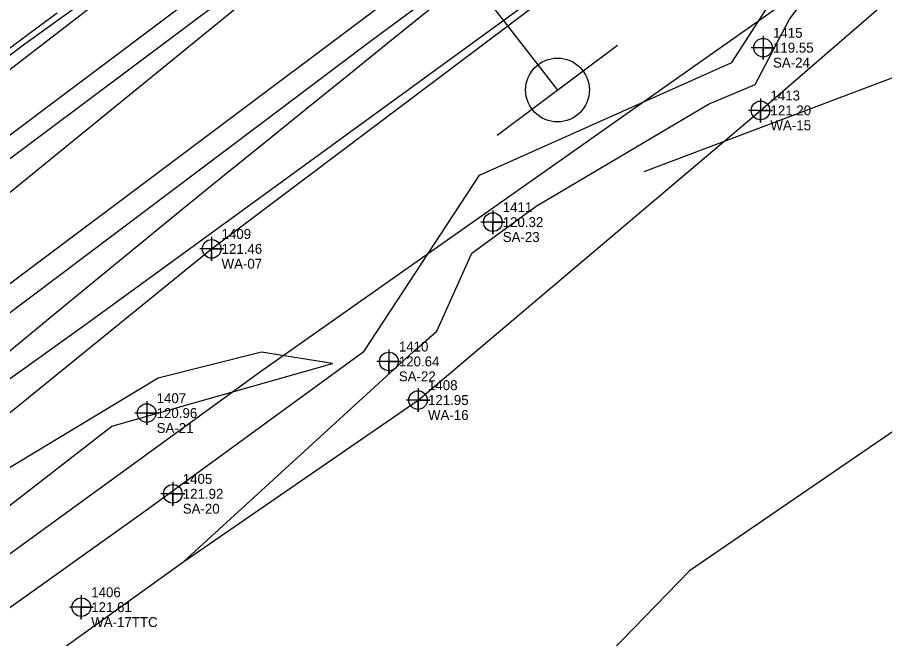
# Model space of a CAD drawing. Extents: x 2186615 to 2188822, y 629899 to 631820.
# Drawn here: x 2187187.8 to 2187253.2, y 630351.9 to 630398.8 of the extents above; entities that cross this region are included whole.
import ezdxf

# ---------------------------------------------------------------- set-up
doc = ezdxf.new("R2010")
doc.units = 0
for name, color, linetype in [('Exist Environmental Wetland Boundary', 7, 'Continuous'), ('Exist Environmental Wetland Boundary Cogo Comment', 7, 'Continuous'), ('Exist Environmental Wetland Boundary Cogo Elevation', 7, 'Continuous'), ('Exist Environmental Wetland Boundary Cogo Number', 7, 'Continuous'), ('Exist Environmental Wetland Boundary Cogo Point CELL', 7, 'Continuous'), ('Exist Environmental Wetland Boundary Leader', 7, 'Continuous'), ('Exist Guardrail', 7, 'Continuous'), ('Exist Hydro Jurisdictional Stream or Body of Water', 7, 'Continuous'), ('Exist Hydro Stream or Body of Water', 7, 'Continuous'), ('Exist Right of Way Line', 7, 'Continuous'), ('Exist Roads EOP', 7, 'Continuous'), ('Exist Roads EOT', 7, 'Continuous'), ('Exist Utilities Sanitary Sewer UG Line', 7, 'Continuous'), ('Exist Utilities Telephone Pole CELL', 7, 'Continuous'), ('Exist Utilities Telephone UG Cable SUE LOS C', 7, 'Continuous'), ('Exist Utilities Telephone UG FO SUE LOS B', 7, 'Continuous'), ('Exist Vegetation Woods Line', 7, 'Continuous'), ('Scratch_Level_1', 7, 'Continuous')]:
    doc.layers.add(name, color=color, linetype=linetype)

msp = doc.modelspace()

# ---------------------------------------------------------------- linework, layer by layer
at = {"layer": 'Exist Environmental Wetland Boundary'}
for points in [[(2187200.333, 630357.676), (2187218.012, 630369.88), (2187243.865, 630391.755), (2187268.738, 630413.3), (2187284.769, 630424.116), (2187304.062, 630440.889), (2187311.728, 630449.237), (2187310.985, 630450.407)], [(2187091.311, 630271.672), (2187085.676, 630287.812), (2187098.271, 630306.167), (2187117.246, 630318.391), (2187145.167, 630331.818), (2187167.383, 630352.861), (2187202.427, 630381.298), (2187228.671, 630401.09), (2187258.21, 630420.516), (2187282.166, 630435.853)]]:
    msp.add_lwpolyline(points, dxfattribs=at)
at = {"layer": 'Exist Environmental Wetland Boundary Cogo Point CELL'}
for points in [[(2187244.056, 630397.391), (2187244.056, 630395.591), (2187244.056, 630396.491), (2187244.956, 630396.491), (2187243.156, 630396.491)], [(2187243.865, 630392.655), (2187243.865, 630390.855), (2187243.865, 630391.755), (2187244.765, 630391.755), (2187242.965, 630391.755)], [(2187223.654, 630384.221), (2187223.654, 630382.421), (2187223.654, 630383.321), (2187224.554, 630383.321), (2187222.754, 630383.321)], [(2187202.427, 630382.198), (2187202.427, 630380.398), (2187202.427, 630381.298), (2187203.327, 630381.298), (2187201.527, 630381.298)], [(2187215.811, 630373.695), (2187215.811, 630371.895), (2187215.811, 630372.795), (2187216.711, 630372.795), (2187214.911, 630372.795)], [(2187218.012, 630370.78), (2187218.012, 630368.98), (2187218.012, 630369.88), (2187218.912, 630369.88), (2187217.112, 630369.88)], [(2187197.525, 630369.798), (2187197.525, 630367.998), (2187197.525, 630368.898), (2187198.425, 630368.898), (2187196.625, 630368.898)], [(2187199.498, 630363.7), (2187199.498, 630361.9), (2187199.498, 630362.8), (2187200.398, 630362.8), (2187198.598, 630362.8)], [(2187192.588, 630355.137), (2187192.588, 630353.337), (2187192.588, 630354.237), (2187193.488, 630354.237), (2187191.688, 630354.237)]]:
    msp.add_lwpolyline(points, dxfattribs=at)
for centre in [(2187244.056, 630396.491), (2187243.865, 630391.755), (2187223.654, 630383.321), (2187202.427, 630381.298), (2187215.811, 630372.795), (2187218.012, 630369.88), (2187197.525, 630368.898), (2187199.498, 630362.8), (2187192.588, 630354.237)]:
    msp.add_circle(centre, 0.703, dxfattribs=at)
at = {"layer": 'Exist Environmental Wetland Boundary Leader'}
msp.add_lwpolyline([(2187235.079, 630387.141), (2187254.322, 630394.422), (2187258.337, 630397.432)], dxfattribs=at)
at = {"layer": 'Exist Guardrail'}
msp.add_lwpolyline([(2187434.115, 630575.844), (2187413.642, 630560.327), (2187392.389, 630544.34), (2187371.189, 630528.329), (2187353.022, 630514.54), (2187332.378, 630498.862), (2187308.035, 630480.517), (2187282.875, 630461.57), (2187260.432, 630444.878), (2187240.787, 630430.164), (2187221.99, 630416.084), (2187199.867, 630399.404), (2187178.435, 630383.307), (2187159.654, 630369.054), (2187143.316, 630356.53), (2187128.809, 630345.412), (2187116.826, 630336.517)], dxfattribs=at)
at = {"layer": 'Exist Hydro Jurisdictional Stream or Body of Water'}
for points in [[(2187197.322, 630361.43), (2187213.945, 630373.562), (2187222.659, 630386.877), (2187241.705, 630395.38), (2187246.836, 630403.358), (2187255.086, 630412.327), (2187267.186, 630417.823), (2187275.409, 630422.294), (2187281.209, 630428.913), (2187281.92, 630435.898), (2187289.055, 630441.644), (2187305.984, 630451.32), (2187327.255, 630464.456), (2187344.34, 630479.914), (2187359.178, 630488.147), (2187368.792, 630495.674), (2187384.724, 630510.856), (2187399.768, 630521.857), (2187428.248, 630541.272), (2187449.565, 630557.041)], [(2187200.333, 630357.676), (2187217.66, 630373.541), (2187219.417, 630375.085), (2187222.068, 630380.972), (2187226.921, 630384.519), (2187239.946, 630392.223), (2187243.455, 630393.717), (2187246.058, 630398.658), (2187250.235, 630404.156), (2187257.633, 630410.563), (2187272.327, 630417.422), (2187280.629, 630425.711), (2187291.154, 630437.828), (2187309.311, 630449.202), (2187326.618, 630461.663), (2187344.871, 630475.57), (2187361.058, 630486.179), (2187383.779, 630505.824), (2187403.688, 630519.913), (2187435.685, 630540.516), (2187447.835, 630554.369)], [(2187113.925, 630297.142), (2187128.079, 630305.06), (2187146.835, 630323.393), (2187171.96, 630343.368), (2187197.322, 630361.43)], [(2187107.375, 630283.147), (2187119.04, 630296.895), (2187130.027, 630302.015), (2187148.417, 630318.795), (2187174.154, 630338.895), (2187200.333, 630357.676)]]:
    msp.add_lwpolyline(points, dxfattribs=at)
at = {"layer": 'Exist Hydro Stream or Body of Water'}
msp.add_lwpolyline([(2187182.978, 630358.658), (2187194.893, 630367.909), (2187211.561, 630372.649), (2187206.205, 630373.5), (2187198.39, 630371.54), (2187179.595, 630360.193), (2187182.978, 630358.658)], dxfattribs=at)
at = {"layer": 'Exist Right of Way Line'}
msp.add_line((2187154.402, 630354.104), (2188538.851, 631392.039), dxfattribs=at)
for radius in [2893.554, 2763.554]:
    msp.add_arc((2189028.8, 628141.736), radius, 125.65722, 135.708207, dxfattribs=at)
at = {"layer": 'Exist Roads EOP'}
msp.add_lwpolyline([(2187255.836, 630446.736), (2187251.071, 630443.09), (2187246.246, 630439.524), (2187241.419, 630435.961), (2187236.591, 630432.398), (2187231.763, 630428.836), (2187226.945, 630425.261), (2187222.134, 630421.675), (2187217.324, 630418.089), (2187212.513, 630414.504), (2187207.703, 630410.918), (2187202.884, 630407.343), (2187198.03, 630403.816), (2187193.174, 630400.292), (2187188.329, 630396.753), (2187183.51, 630393.178)], dxfattribs=at)
at = {"layer": 'Exist Roads EOT'}
msp.add_lwpolyline([(2187190.768, 630399.105), (2187188.763, 630397.612), (2187186.758, 630396.118)], dxfattribs=at)
at = {"layer": 'Exist Utilities Sanitary Sewer UG Line'}
msp.add_line((2186953.526, 630213.342), (2187280.261, 630457.751), dxfattribs=at)
at = {"layer": 'Exist Utilities Telephone Pole CELL'}
for p, q in [((2187223.995, 630389.898), (2187233.071, 630396.693)), ((2187228.538, 630393.299), (2187228.538, 630393.299))]:
    msp.add_line(p, q, dxfattribs=at)
msp.add_circle((2187228.538, 630393.299), 2.407, dxfattribs=at)
at = {"layer": 'Exist Utilities Telephone UG Cable SUE LOS C'}
msp.add_lwpolyline([(2187048.711, 630267.562), (2187045.354, 630278.254), (2187057.018, 630287.248), (2187078.192, 630303.416), (2187102.037, 630322.514), (2187119.945, 630336.137), (2187137.937, 630349.883), (2187161.709, 630367.862), (2187186.024, 630384.639), (2187207.077, 630401.804), (2187231.599, 630419.787), (2187256.848, 630438.711), (2187278.852, 630453.798), (2187296.978, 630467.542), (2187304.942, 630472.732), (2187317.617, 630478.554), (2187327.51, 630484.53), (2187332.683, 630485.862), (2187337.992, 630482.804), (2187346.28, 630476.796)], dxfattribs=at)
at = {"layer": 'Exist Utilities Telephone UG FO SUE LOS B'}
for points in [[(2187129.463, 630527.757), (2187139.462, 630503.378), (2187147.833, 630484.704), (2187152.044, 630478.591), (2187166.914, 630468.201), (2187180.789, 630460.122), (2187192.399, 630446.464), (2187206.004, 630427.517), (2187215.398, 630412.656), (2187218.537, 630406.182), (2187228.538, 630393.279)], [(2187049.385, 630270.146), (2187042.504, 630278.367), (2187044.061, 630284.337), (2187057.315, 630294.022), (2187075.644, 630307.116), (2187098.729, 630326.668), (2187116.947, 630341.492), (2187134.442, 630355.423), (2187157.809, 630373.051), (2187181.899, 630390.785), (2187205.122, 630408.701), (2187231.973, 630429.319), (2187252.444, 630444.703), (2187272.54, 630459.689), (2187294.094, 630476.316), (2187309.645, 630487.965), (2187327.188, 630501.034), (2187332.668, 630500.224), (2187340.344, 630491.389), (2187346.28, 630476.796)]]:
    msp.add_lwpolyline(points, dxfattribs=at)
at = {"layer": 'Exist Vegetation Woods Line'}
for points in [[(2187105.726, 630299.086), (2187150.799, 630331.829), (2187206.105, 630372.034), (2187256.074, 630407.258), (2187300.913, 630439.289), (2187349.475, 630473.877), (2187396.874, 630507.865), (2187440.691, 630538.214), (2187466.075, 630555.071), (2187474.722, 630557.755), (2187481.166, 630558.923), (2187486.051, 630559.676), (2187489.303, 630561.136), (2187491.384, 630563.953), (2187492.451, 630570.166), (2187494.251, 630572.315)], [(2187473.569, 630527.3), (2187453.75, 630512.916), (2187435.186, 630501.319), (2187410.074, 630490.236), (2187391.303, 630473.708), (2187377.298, 630457.794), (2187368.165, 630449.57), (2187357.71, 630447.66), (2187342.586, 630438.232), (2187325.212, 630423.547), (2187317.288, 630416.779), (2187299.412, 630410.909), (2187286.374, 630395.698), (2187276.981, 630383.819), (2187255.826, 630368.846), (2187238.494, 630356.985), (2187221.565, 630339.526), (2187197.373, 630321.295), (2187174.715, 630306.11), (2187151.591, 630284.746), (2187135.361, 630271.561)], [(2187230.496, 630408.889), (2187277.266, 630443.245), (2187318.865, 630473.262), (2187330.634, 630477.313), (2187307.147, 630458.864), (2187234.208, 630405.639), (2187193.004, 630375.627), (2187170.079, 630359.227), (2187132.552, 630332.436), (2187105.521, 630312.125)], [(2187103.491, 630315.876), (2187138.523, 630340.833), (2187186.53, 630376.001), (2187214.458, 630397), (2187230.496, 630408.889)]]:
    msp.add_lwpolyline(points, dxfattribs=at)
at = {"layer": 'Scratch_Level_1'}
msp.add_arc((2189028.8, 628141.736), 2815.554, 125.65722, 135.708207, dxfattribs=at)

# ---------------------------------------------------------------- texts
at = {"layer": 'Exist Environmental Wetland Boundary Cogo Comment'}
for s, p in [('SA-24', (2187244.806, 630394.991)), ('WA-15', (2187244.615, 630390.255)), ('SA-23', (2187224.404, 630381.821)), ('WA-07', (2187203.177, 630379.798)), ('SA-22', (2187216.561, 630371.295)), ('WA-16', (2187218.762, 630368.38)), ('SA-21', (2187198.275, 630367.398)), ('SA-20', (2187200.248, 630361.3)), ('WA-17TTC', (2187193.338, 630352.737))]:
    msp.add_text(s, height=0.75, dxfattribs=at).set_placement(p)
at = {"layer": 'Exist Environmental Wetland Boundary Cogo Elevation'}
for s, p in [('119.55', (2187244.806, 630396.116)), ('121.20', (2187244.615, 630391.38)), ('120.32', (2187224.404, 630382.946)), ('121.46', (2187203.177, 630380.923)), ('120.64', (2187216.561, 630372.42)), ('121.95', (2187218.762, 630369.505)), ('120.96', (2187198.275, 630368.523)), ('121.92', (2187200.248, 630362.425)), ('121.61', (2187193.338, 630353.862))]:
    msp.add_text(s, height=0.75, dxfattribs=at).set_placement(p)
at = {"layer": 'Exist Environmental Wetland Boundary Cogo Number'}
for s, p in [('1415', (2187244.806, 630397.241)), ('1413', (2187244.615, 630392.505)), ('1411', (2187224.404, 630384.071)), ('1409', (2187203.177, 630382.048)), ('1410', (2187216.561, 630373.545)), ('1408', (2187218.762, 630370.63)), ('1407', (2187198.275, 630369.648)), ('1405', (2187200.248, 630363.55)), ('1406', (2187193.338, 630354.987))]:
    msp.add_text(s, height=0.75, dxfattribs=at).set_placement(p)

doc.saveas('drawing.dxf')
